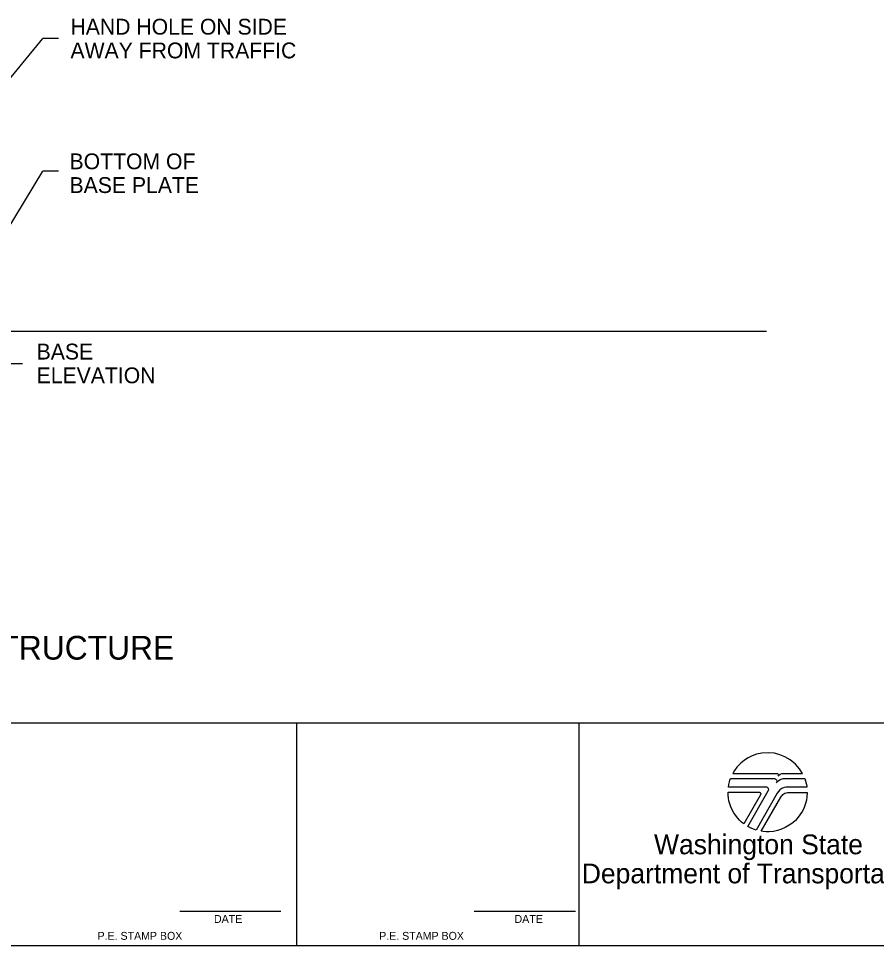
# Model space of a CAD drawing. Extents: x 99862 to 104211, y 98939 to 111076.
# Drawn here: x 101494 to 102361, y 103000 to 103937 of the extents above; entities that cross this region are included whole.
import ezdxf

# ---------------------------------------------------------------- set-up
doc = ezdxf.new("R2010")
doc.units = 0
for name, color, linetype in [('Level 15', 7, 'Continuous'), ('Level 2', 7, 'Continuous'), ('Level 20', 7, 'Continuous'), ('Level 60', 7, 'Continuous'), ('Level 7', 7, 'Continuous')]:
    doc.layers.add(name, color=color, linetype=linetype)

msp = doc.modelspace()

# ---------------------------------------------------------------- linework, layer by layer
at = {"layer": 'Level 15'}
for p, q in [((101346.04, 103706.86), (101518.38, 103916.54)), ((101534.38, 103916.54), (101518.38, 103916.54)), ((101445.5, 103662.4), (101518.38, 103782.42)), ((101534.38, 103782.42), (101518.38, 103782.42)), ((101497.9, 103587.85), (101481.9, 103587.85))]:
    msp.add_line(p, q, dxfattribs=at)
at = {"layer": 'Level 60'}
for p, q in [((100000, 103225), (103150, 103225)), ((101775.14, 103000), (101775.14, 103225)), ((102060.14, 103225), (102060.14, 103000)), ((101656.73, 103034.63), (101759, 103034.63)), ((101954.38, 103034.63), (102056.64, 103034.63)), ((100000, 103000), (103150, 103000))]:
    msp.add_line(p, q, dxfattribs=at)
for points in [[(102215.65, 103173.9), (102259.93, 103173.9), (102260.72, 103173.72), (102261.37, 103173.19), (102261.67, 103172.58), (102261.73, 103172.01), (102261.49, 103171.19), (102262.28, 103172.2), (102263.47, 103173.12), (102265.22, 103173.79), (102266.37, 103173.9), (102285.93, 103173.91), (102283.01, 103178.5), (102278.88, 103183.29), (102273.75, 103187.57), (102268.34, 103190.76), (102263.32, 103192.81), (102257.62, 103194.23), (102251.64, 103194.81), (102245.06, 103194.41), (102239.72, 103193.26), (102235.06, 103191.6), (102231.09, 103189.63), (102227.31, 103187.2), (102223.74, 103184.28), (102219.78, 103180.08), (102217.47, 103176.94)], [(102215.65, 103173.9), (102259.93, 103173.9), (102260.72, 103173.72), (102261.37, 103173.19), (102261.67, 103172.58), (102261.73, 103172.01), (102261.49, 103171.19), (102262.28, 103172.2), (102263.47, 103173.12), (102265.22, 103173.79), (102266.37, 103173.9), (102285.93, 103173.91), (102283.01, 103178.5), (102278.88, 103183.29), (102273.75, 103187.57), (102268.34, 103190.76), (102263.32, 103192.81), (102257.62, 103194.23), (102251.64, 103194.81), (102245.06, 103194.41), (102239.72, 103193.26), (102235.06, 103191.6), (102231.09, 103189.63), (102227.31, 103187.2), (102223.74, 103184.28), (102219.78, 103180.08), (102217.47, 103176.94)], [(102213.29, 103168.72), (102257.21, 103168.71), (102257.88, 103168.64), (102258.46, 103168.44), (102258.93, 103168.16), (102259.22, 103167.93), (102259.69, 103167.35), (102260.04, 103166.62), (102260.18, 103165.95), (102260.12, 103165.22), (102259.97, 103164.68), (102259.72, 103164.19), (102260.25, 103164.92), (102261.1, 103165.91), (102262.11, 103166.78), (102263.44, 103167.62), (102264.65, 103168.15), (102266.49, 103168.61), (102269.17, 103168.71), (102288.29, 103168.71), (102289.11, 103166.24), (102289.58, 103164.53), (102289.98, 103162.72), (102290.31, 103160.88), (102290.43, 103160.06), (102272.02, 103160.06), (102269.5, 103160.01), (102267.71, 103159.7), (102265.21, 103158.68), (102263.18, 103157.22), (102261.82, 103155.71), (102260.6, 103153.75), (102239.14, 103116.61), (102236.5, 103117.51), (102234.2, 103118.47), (102232.2, 103119.45), (102230.68, 103120.29), (102251.54, 103156.11), (102251.93, 103157.41), (102251.64, 103158.57), (102250.69, 103159.64), (102249.9, 103159.98), (102249.27, 103160.06), (102211.15, 103160.06), (102211.57, 103162.58), (102211.83, 103163.87), (102212.19, 103165.26), (102212.72, 103167.04)], [(102210.8, 103154.85), (102242.31, 103154.84), (102242.71, 103154.79), (102243.19, 103154.59), (102243.46, 103154.37), (102243.71, 103154.07), (102243.86, 103153.74), (102243.95, 103153.34), (102243.92, 103152.86), (102243.73, 103152.37), (102226.65, 103122.98), (102224.53, 103124.7), (102222.55, 103126.55), (102220.7, 103128.52), (102218.31, 103131.53), (102216.6, 103134.12), (102215, 103137.03), (102213.59, 103140.19), (102212.6, 103143.04), (102211.8, 103146), (102211.24, 103149.02), (102210.92, 103151.96)], [(102244.22, 103115.41), (102264.18, 103149.96), (102264.77, 103150.86), (102265.42, 103151.65), (102266.29, 103152.48), (102267.18, 103153.15), (102268.34, 103153.8), (102269.51, 103154.27), (102270.8, 103154.58), (102271.5, 103154.68), (102272.42, 103154.72), (102290.77, 103154.71), (102290.51, 103150.33), (102289.96, 103146.87), (102288.82, 103142.52), (102287.62, 103139.29), (102285.98, 103135.88), (102283.5, 103131.87), (102280.8, 103128.43), (102278.86, 103126.38), (102276.15, 103123.94), (102272.71, 103121.41), (102268.67, 103119.09), (102265.01, 103117.48), (102260.85, 103116.15), (102256.85, 103115.33), (102252.39, 103114.9), (102249.21, 103114.9), (102246.3, 103115.12)]]:
    msp.add_lwpolyline(points, close=True, dxfattribs=at)
at = {"layer": 'Level 7'}
msp.add_line((101340.5, 103620.89), (102249.7, 103620.89), dxfattribs=at)

# ---------------------------------------------------------------- texts
at = {"layer": 'Level 2'}
for s, p in [('BOTTOM OF', (101545.44, 103784.47)), ('BASE PLATE', (101545.44, 103760.47))]:
    msp.add_text(s, height=16, rotation=360, dxfattribs=at).set_placement(p)
at = {"layer": 'Level 20'}
for s, p in [('HAND HOLE ON SIDE', (101546.38, 103920.54)), ('AWAY FROM TRAFFIC', (101546.38, 103896.54)), ('BASE', (101512.2, 103592.19)), ('ELEVATION', (101512.2, 103568.19))]:
    msp.add_text(s, height=16, rotation=360, dxfattribs=at).set_placement(p)
msp.add_text('DOUBLE CANTILEVER SIGN STRUCTURE', height=24, dxfattribs=at).set_placement((101014.49, 103288.89))
at = {"layer": 'Level 60'}
for s, height, p in [('Washington State', 19.999, (102136.05, 103092.17)), ('Department of Transportation', 19.999, (102063.07, 103062.8)), ('DATE', 8.032, (101691.37, 103022.78)), ('DATE', 8.032, (101995.07, 103022.78)), ('P.E. STAMP BOX', 8, (101573.79, 103005.71)), ('P.E. STAMP BOX', 8, (101858.35, 103005.71))]:
    msp.add_text(s, height=height, dxfattribs=at).set_placement(p)

doc.saveas('drawing.dxf')
